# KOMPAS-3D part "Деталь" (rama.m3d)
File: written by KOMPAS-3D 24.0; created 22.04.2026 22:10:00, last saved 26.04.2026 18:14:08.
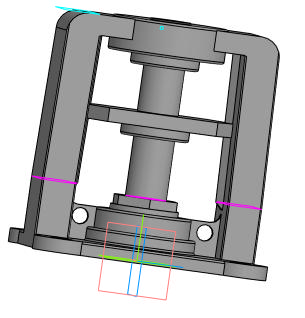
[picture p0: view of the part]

Document properties: Автор: mrdid; Полное имя файла: C:\Работа\ГОТОВЫЕ ИСХОДНИКИ\VSO2130M-F-S Клапан запорный сильфонный DN.ru Ду15-100 Ру40\исходные материалы\DN100\rama.m3d

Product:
- Part/product: Деталь
    Масса: 9.446861

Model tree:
1. Эскиз:2  (with: Ребро.Элемент выдавливания:14)
2. Элемент выдавливания:1
     Расстояние 1 = 10
3. Эскиз:3  (with: Грань.Элемент выдавливания:1, Ребро.Элемент выдавливания:1)
4. Элемент выдавливания:2
     Расстояние 2 = 10
5. Эскиз:4  (with: Грань.Элемент выдавливания:1)
6. Элемент выдавливания:3
     Расстояние 1 = 10
7. Эскиз:5  (with: Грань.Элемент выдавливания:3, Ребро.Элемент выдавливания:3)
8. Элемент выдавливания:4
     Расстояние 1 = 15
9. Эскиз:6  (with: Грань.Элемент выдавливания:1, Ребро.Элемент выдавливания:1)
10. Элемент выдавливания:5
     Расстояние 1 = 40
11. Эскиз:23  (with: Грань.Элемент выдавливания:4, Ребро.Элемент выдавливания:4)
12. Элемент выдавливания:21
     Расстояние 1 = 11
13. Эскиз:7  (with: Грань.Элемент выдавливания:21, Ребро.Элемент выдавливания:3)
14. Элемент выдавливания:6
     Расстояние 2 = 7
15. Эскиз:8  (with: Грань.Элемент выдавливания:5, Ребро.Элемент выдавливания:5)
16. Смещенная плоскость:1  (with: Грань.Элемент выдавливания:5)
17. Эскиз:9
18. Элемент по сечениям:1
19. Элемент по сечениям:2
20. Эскиз:10
21. Элемент выдавливания:8
     Расстояние 2 = 15
22. Эскиз:11  (with: Грань.Элемент выдавливания:8, Ребро.Элемент выдавливания:3)
23. Элемент выдавливания:9  (with: Грань.Элемент выдавливания:8)
     Расстояние 1 = 1; Расстояние 2 = 24; Смещение 2 = 9
24. Эскиз:12  (with: Грань.Элемент выдавливания:9, Ребро.Элемент выдавливания:9)
25. Элемент выдавливания:10
     Расстояние 1 = 8
26. Эскиз:13  (with: Грань.Элемент выдавливания:21, Ребро.Элемент выдавливания:3)
27. Элемент выдавливания:11  (with: Грань.Элемент выдавливания:10)
     Расстояние 1 = 95.84
28. Смещенная плоскость:2  (with: Грань.Элемент выдавливания:21)
29. Эскиз:14  (with: Ребро.Элемент по сечениям:2, Ребро.Элемент по сечениям:1)
30. Элемент выдавливания:12
     Расстояние 1 = 10
31. Эскиз:15  (with: Грань.Элемент выдавливания:12, Ребро.Элемент выдавливания:3)
32. Элемент выдавливания:13
     Расстояние 1 = 8
33. Эскиз:16  (with: Ребро.Элемент выдавливания:5, Ребро.Элемент выдавливания:1, Ребро.Элемент выдавливания:4)
34. Элемент выдавливания:14
     Расстояние 1 = 4
35. Элемент выдавливания:15
     Расстояние 1 = 2
36. Эскиз:17  (with: Ребро.Элемент выдавливания:14, Ребро.Элемент выдавливания:5)
37. Элемент выдавливания:16
     Расстояние 1 = 86; Расстояние 2 = 86
38. Скругление:1  (with: Ребро.Элемент выдавливания:1, Ребро.Элемент выдавливания:3)
     Радиус = 1.5
39. Скругление:2  (with: Ребро.Элемент выдавливания:9, Ребро.Элемент выдавливания:10, Ребро.Элемент выдавливания:4, Ребро.Элемент выдавливания:13)
40. Эскиз:18  (with: Грань.Элемент выдавливания:9)
41. Элемент выдавливания:17
     Расстояние 1 = 1
42. Скругление:3  (with: Ребро.Элемент по сечениям:2, Ребро.Элемент по сечениям:1)
     Радиус = 15
43. Скругление:4  (with: Ребро.Элемент выдавливания:8)
     Радиус = 0.5
44. Скругление:5  (with: Ребро.Элемент выдавливания:14)
     Радиус = 7
45. Эскиз:19  (with: Ребро.Элемент выдавливания:17)
46. Элемент выдавливания:18  (with: Грань.Элемент выдавливания:9)
     Смещение 1 = 5
47. Смещенная плоскость:3  (with: Грань.Элемент выдавливания:18)
     Расстояние = 2
48. Эскиз:20  (with: Ребро.Элемент выдавливания:18)
49. Элемент выдавливания:19
     Расстояние 2 = 0.2
50. Скругление:6  (with: Ребро.Элемент выдавливания:18)
     Радиус = 1
51. Эскиз:21  (with: Ребро.Элемент выдавливания:19)
52. Элемент выдавливания:20
     Расстояние 1 = 10
53. Скругление:7  (with: Ребро.Элемент по сечениям:2, Ребро.Элемент выдавливания:5, Ребро.Элемент по сечениям:1)
     Радиус = 1
54. Фаска:1  (with: Ребро.Элемент по сечениям:1, Ребро.Элемент по сечениям:2)
     Угол = 45; Длина 1 = 5; Длина 2 = 5
55. Массив по концентрической сетке:1  (with: Элемент выдавливания:2, Эскиз:3)  (labels: Клапан запорный DN.ru Ду100 Ру40)  (4 pattern instances)
     Шаг 2 = 360

Expressions: DN/2; v249/2; DN/3; DN/4
Referenced files in C:\Работа\ГОТОВЫЕ ИСХОДНИКИ\VSO2130M-F-S Клапан запорный сильфонный DN.ru Ду15-100 Ру40\исходные материалы\DN100\: VSO2130M-F-S Клапан запорный DN.ru Ду100 Ру40.a3d
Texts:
  DN+5
  DN-20
  DN-15
  DN-40
  Ось Y.Начало координат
